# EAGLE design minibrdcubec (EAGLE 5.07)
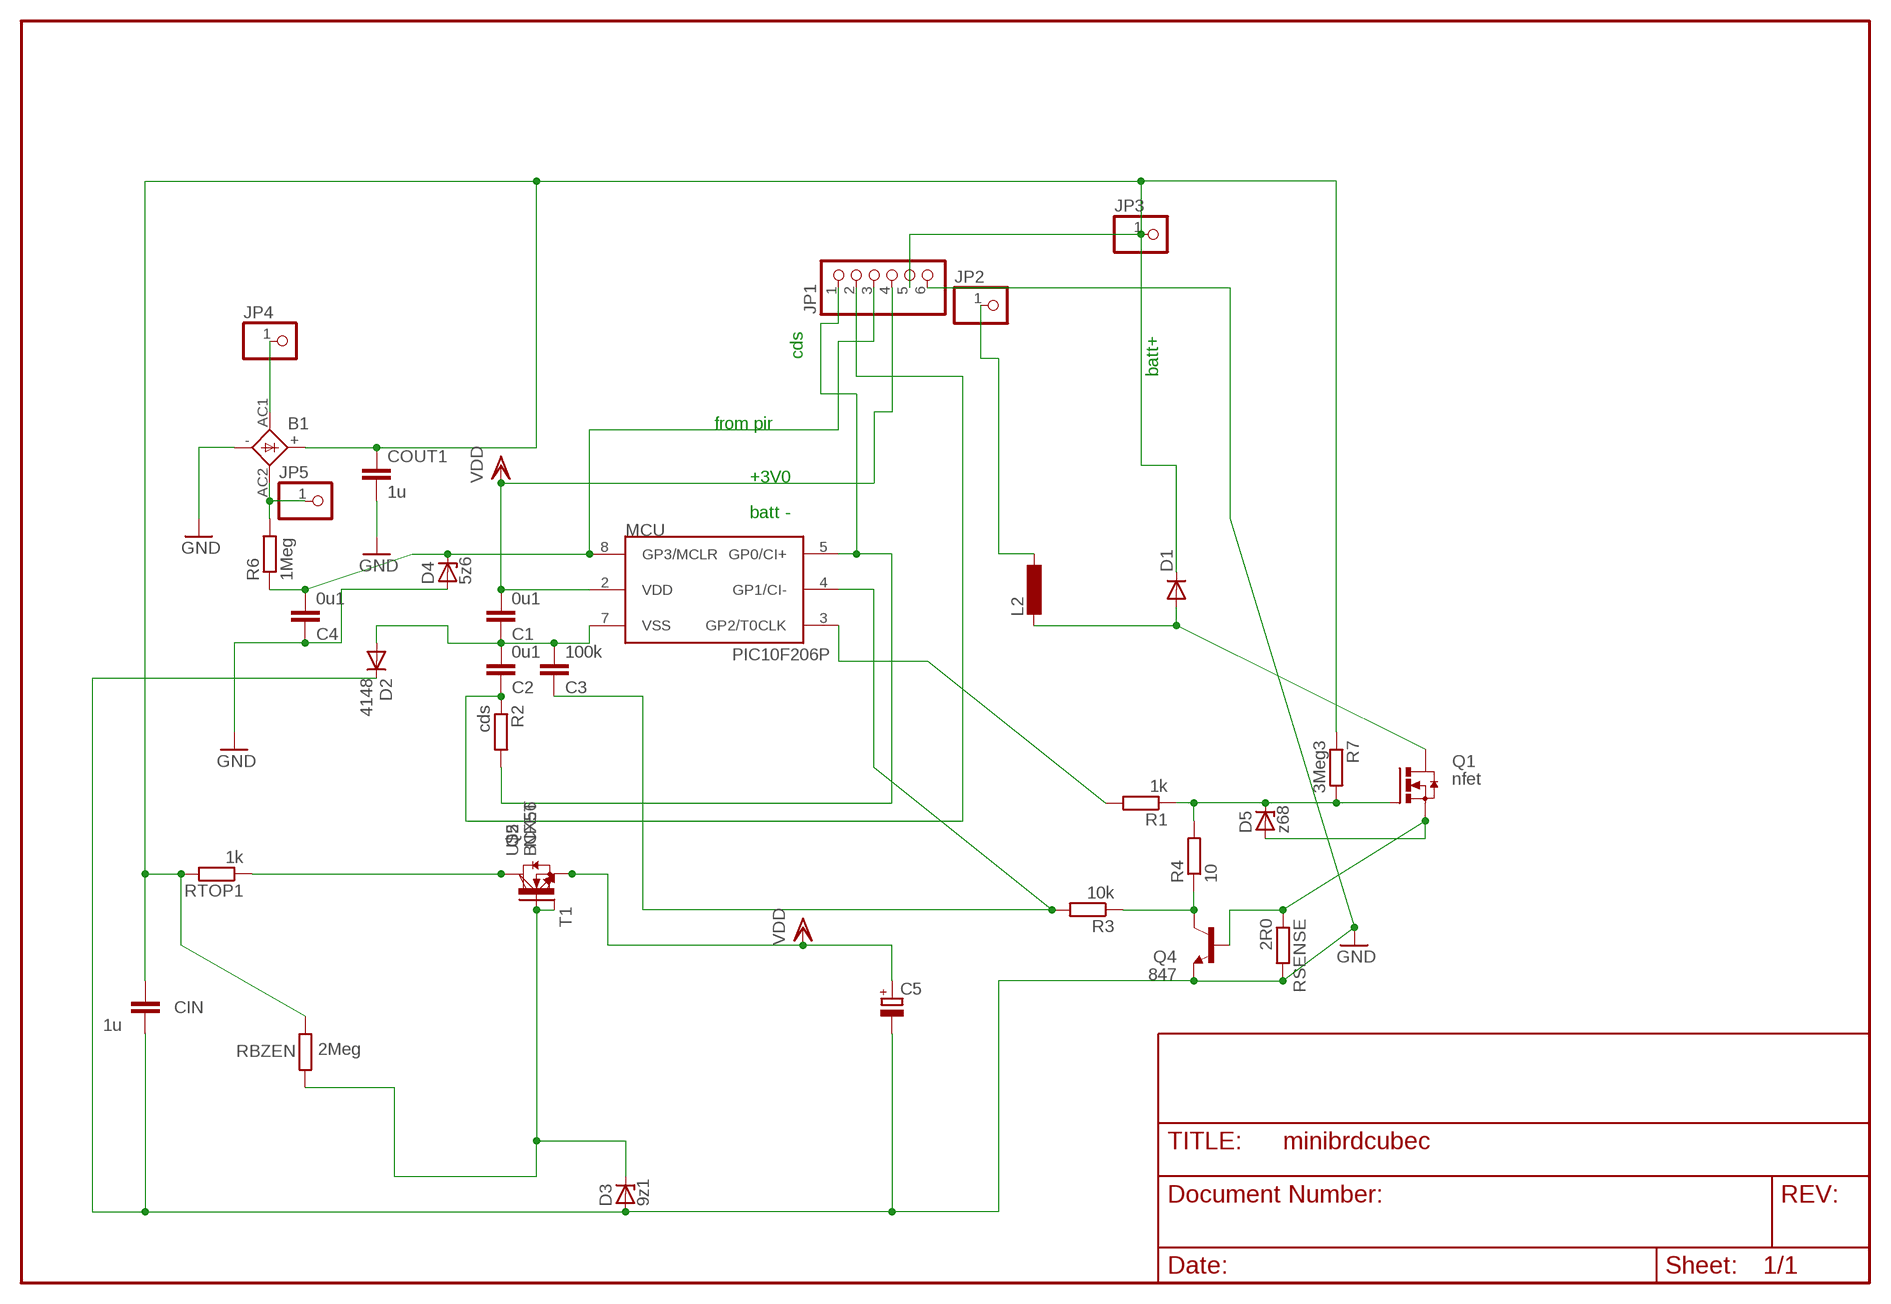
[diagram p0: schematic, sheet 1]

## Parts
B1  1KAB  [1KAB]
C1  0u1  C-EUC1206  [C1206]
C2  0u1  C-EUC0805  [C0805]
C3  100k  C-EUC1206  [C1206]
C4  0u1  C-EUC1206  [C1206]
C5  CPOL-EUSANYO_SMD_B6  [SANYO-OSCON_SMD_B6]
CIN  1u  C-EU050-024X044  [C050-024X044]
COUT1  1u  C-EU075-032X103  [C075-032X103]
D1  DIODE-SMC  [SMC]
D2  4148  1N4148MINIMELF  [MINIMELF]
D3  9z1  ZENER-DIODESOD80C  [SOD80C]
D4  5z6  ZENER-DIODESOD80C  [SOD80C]
D5  z68  ZENER-DIODESOD80C  [SOD80C]
JP1  PINHD-1X6  [1X06BOX]
JP2  PINHD-1X11X0.4  [1X01]
JP3  PINHD-1X11X0.4  [1X01]
JP4  PINHD-1X11X0.4  [1X01]
JP5  PINHD-1X11X0.4  [1X01]
L2  L-EU0207-17  [0207/17L]
MCU  PIC10F206P  [DIL8]
Q1  nfet  N-HEXFET_DPAK-  [TO252]
Q4  847  BC847ASMD  [SOT23]
Q5  NFET  N-HEXFET_DPAK-  [TO252]
R1  1k  R-EU_R0805  [R0805]
R2  cds  R-EU_0204/2V  [0204V]
R3  10k  R-EU_R1206  [R1206]
R4  10  R-EU_R0603  [R0603]
R6  1Meg  R-EU_0207/20  [0207/20]
R7  3Meg3  R-EU_0207/10  [0207/10]
RBZEN  2Meg  R-EU_0204/7  [0204/7]
RSENSE  2R0  R-EU_0207/15  [0207/15]
RTOP1  1k  R-EU_R1206  [R1206]
T1  -NPN-TO126V  [TO126V]
U$2  BCX56  [SOT223]

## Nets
AC1: B1.AC1 JP4.1
AC2: B1.AC2 JP5.1 R6.2
C: Q5.3(D) RTOP1.1 T1.2(C) U$2.2(C)
CB: D3.C Q5.1(G) RBZEN.2 T1.3(B) U$2.1(B)
GND: B1.- C4.1 C5.- CIN.2 COUT1.2 D2.C D3.A D4.A JP1.6 Q4.2(E) RSENSE.2
HOT: D1.A L2.2 Q1.3(D)
LED-: JP2.1 L2.1
N$1: Q4.3(C) R3.1 R4.1
N$2: JP1.1 MCU.5(GP0/CI+) R2.2
N$3: C1.1 C2.2 C3.2 D2.A MCU.7(VSS)
N$4: C3.1 MCU.4(GP1/CI-) R3.2
N$6: C4.2 D4.C JP1.3 MCU.8(GP3/MCLR) R6.1
N$7: D5.C Q1.1(G) R1.1 R4.2 R7.2
N$11: C2.1 JP1.2 R2.1
N$14: MCU.3(GP2/T0CLK) R1.2
N$17: D5.A Q1.2(S) Q4.1(B) RSENSE.1
VDD: C1.2 C5.+ JP1.4 MCU.2(VDD) Q5.2(S) T1.1(E) U$2.3(E)
VPLUS: B1.+ CIN.1 COUT1.1 D1.C JP1.5 JP3.1 R7.1 RBZEN.1 RTOP1.2

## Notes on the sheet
- cds
- batt+
- from pir
- +3V0
- batt -

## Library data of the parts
B1 = rectifier:1KAB: RECTIFIER grid 5,08 x 5,08 mm
C1-C4 CIN COUT1 = rcl:C-EU: CAPACITOR, European symbol
C5 = rcl-2:CPOL-EU: POLARIZED CAPACITOR, European symbol
D1 = diode-1:DIODE-: DIODE
D2 = diode-1:1N4148: DIODE
D3-D5 = diode:ZENER-DIODE: Z-Diode
JP1 = pinhead:PINHD-1X6: PIN HEADER
JP2-JP5 = pinhead:PINHD-1X1: PIN HEADER
L2 = rcl:L-EU: INDUCTOR, European symbol
MCU = microchip-3:PIC10F2*: uPC nW 0,25/0,5k Program Flash memory Comparator
Q1 Q5 = transistor-power:N-HEXFET_?-*: HEXFET® Power MOSFET
Q4 = transistor-npn:BC847*: NPN Transistor
R1-R4 R7 RBZEN RSENSE RTOP1 = rcl:R-EU_: RESISTOR, European symbol
R6 = rcl-2:R-EU_: RESISTOR, European symbol
T1 = transistor:*-NPN-: NPN Transistror BF959 corrected 2008.03.06
U$2 = transistor-power:BCX56

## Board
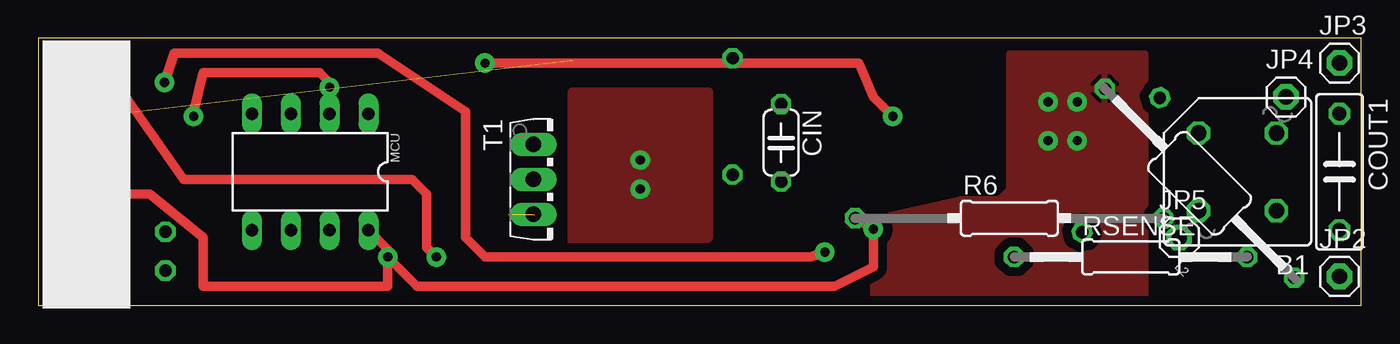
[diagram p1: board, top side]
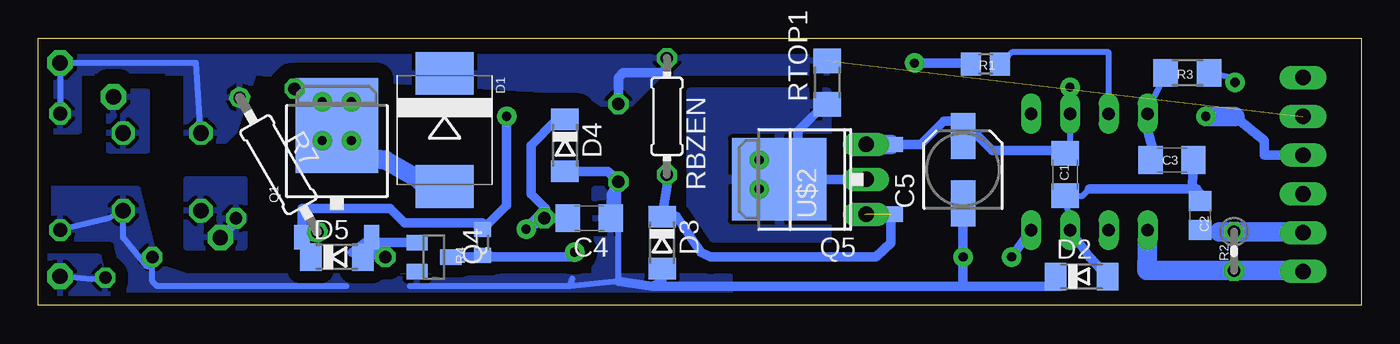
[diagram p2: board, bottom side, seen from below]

Size 86.52 x 17.5 mm. Coordinates in mm from the lower left corner, seen from the top.
Outline: 0,0 86.52,0 86.52,17.5 0,17.5 0,0
Copper layers (1*16): Top 0.035mm / dielectric 1.5mm / Bottom 0.035mm
Design rules "default *": minimum track width 10mil, minimum drill 24mil, track to track 8mil, track to pad 8mil, pad to pad 8mil, via to via 8mil, smd to smd 8mil, copper to edge 20mil, drill to drill 8mil, minimum pad ring 10mil, minimum via ring 8mil, stop-mask expansion 4mil, vias tented up to drill 0mil, thermal gap 10mil

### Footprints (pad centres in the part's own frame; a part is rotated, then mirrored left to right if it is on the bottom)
1KAB = drill 1.016 octagon: + 2.54,-2.54; - -2.54,2.54; AC1 -2.54,-2.54; AC2 2.54,2.54
C1206 = smd 1.6 x 1.8: 1 -1.4,0; 2 1.4,0
C0805 = smd 1.3 x 1.5: 1 -0.95,0; 2 0.95,0
SANYO-OSCON_SMD_B6 = smd 3 x 1.6: + 2.2,0; - -2.2,0
C050-024X044 = drill 0.813 octagon: 1 -2.54,0; 2 2.54,0
C075-032X103 = drill 0.914 octagon: 1 -3.81,0; 2 3.81,0
SMC = smd 2.8 x 3.8: A 3.7,0; C -3.7,0
MINIMELF = smd 1.4 x 1.8: A 1.7,0; C -1.7,0
SOD80C = smd 1.4 x 1.8: A 1.7,0; C -1.7,0
1X06BOX = drill 1.016 long: 1 -6.35,0; 2 -3.81,0; 3 -1.27,0; 4 1.27,0; 5 3.81,0; 6 6.35,0
1X01 = drill 1 pad 1.676 octagon: 1 0,0
0207/17L = drill 0.813 octagon: 1 -8.75,0; 2 8.75,0
DIL8 = drill 0.813 long: 1 -3.81,-3.81; 2 -1.27,-3.81; 3 1.27,-3.81; 4 3.81,-3.81; 5 3.81,3.81; 6 1.27,3.81; 7 -1.27,3.81; 8 -3.81,3.81
TO252 = smd 1 x 1.6: 1 -2.28,-3.53; 2 2.28,-3.53 | smd 5.4 x 6.2: 3 0,3.77
SOT23 = smd 1 x 1.4: 1 -0.95,-1.1; 2 0.95,-1.1; 3 0,1.1
R0805 = smd 1.3 x 1.5: 1 -0.95,0; 2 0.95,0
0204V = drill 0.813 octagon: 1 -1.27,0; 2 1.27,0
R1206 = smd 1.6 x 1.803: 1 -1.422,0; 2 1.422,0
R0603 = smd 1 x 1.1: 1 -0.85,0; 2 0.85,0
0207/20 = drill 0.813 octagon: 1 -10.08,0; 2 10.08,0
0207/10 = drill 0.813 octagon: 1 -5.08,0; 2 5.08,0
0204/7 = drill 0.813 octagon: 1 -3.81,0; 2 3.81,0
0207/15 = drill 0.813 octagon: 1 -7.62,0; 2 7.62,0
TO126V = drill 1.016 long: 1 -2.286,-1.27; 2 0,-1.27; 3 2.286,-1.27
SOT223 = smd 1.219 x 2.235: 1 -2.311,-3.099; 2 0,-3.099; 3 2.311,-3.099 | smd 3.6 x 2.2: 4 0,3.099

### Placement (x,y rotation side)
B1  78.42,8.75 180 top
C1  19.37,8.57 90 bottom
C2  10.54,5.91 90 bottom
C3  12.38,9.53 0 bottom
C4  50.48,5.71 180 bottom
C5  26.04,8.89 90 bottom
CIN  48.58,10.65 270 top
COUT1  85.09,8.75 270 top
D1  59.94,11.49 270 bottom
D2  18.3,1.91 0 bottom
D3  45.72,4.13 270 bottom
D4  52.07,10.48 270 bottom
D5  66.99,3.17 0 bottom
JP1  3.81,8.57 90 top
JP2  85.09,1.91 0 top
JP3  85.09,15.88 0 top
JP4  81.6,13.65 0 top
JP5  74.61,4.45 0 top
L2  75.94,8.01 135 top
MCU  17.78,8.75 180 top
Q1  66.99,8 0 bottom
Q4  60.64,3.17 270 bottom
Q5  34.29,8.26 90 bottom
R1  24.57,15.81 0 bottom
R2  8.32,3.56 270 bottom
R3  11.37,15.24 180 bottom
R4  57.47,4.13 90 bottom
R6  63.5,5.71 0 top
R7  70.8,9.21 300 bottom
RBZEN  45.4,12.38 270 bottom
RSENSE  71.44,3.17 0 top
RTOP1  34.92,14.61 90 bottom
T1  33.66,8.26 270 top
U$2  35.56,8.26 90 bottom

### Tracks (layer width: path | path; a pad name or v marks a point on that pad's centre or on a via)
AC1
  pour Bottom (isolate 0.61): 79.38,13.97 81.92,13.97 81.92,10.16 79.38,10.16
AC2
  Bottom 0.406: B1.AC2 75.42,6.35
  Bottom 0.61: R6.2 73.58,5.48 JP5.1
  pour Bottom (isolate 0.813, rank 2): 73.03,3.81 73.03,8.26 76.83,8.26 76.83,3.81
C  (via drill 0.6 pad 1.27)
  Bottom 0.406: T1.2 U$2.2 | v39.37,9.53 38.73,9.53 38.73,8.89
  Bottom 0.61: 38.73,8.89 38.1,8.26 36.83,8.26 | U$2.2 36.83,8.26 | RTOP1.1 35.08,13.18 36.83,11.43 36.83,8.26
  other vias: 39.37,7.62
  pour Bottom (isolate 0.61, rank 4): 34.92,13.97 43.81,13.97 43.81,12.06 43.81,4.45 42.55,3.17 34.92,3.17
  pour Top (isolate 0.61, rank 4): 34.92,13.97 43.81,13.97 43.81,12.06 43.81,4.45 42.55,3.17 34.92,3.17
CB  (2 unrouted)
  Bottom 0.61: Q5.1 30.76,4.09 31.75,3.17 42.55,3.17 43.18,3.49 44.77,5.83 D3.C 45.4,7.79 RBZEN.2
  Bottom 1.27: T1.3
GND  (via drill 0.6 pad 1.27)
  Top 0.61: JP1.6 4.13,14.61 5.08,14.61 9.53,8.26 24.45,8.26 25.4,7.3 25.4,3.81 v26.04,3.17
  Bottom 0.406: 66.36,1.27 78.74,1.27 79.06,1.59 RSENSE.2 79.38,2.54 80.96,4.45 B1.- 81.92,5.71 COUT1.2 | 51.75,1.27 48.58,1.59 CIN.2 | 51.75,1.27 62.23,1.27 | 19.68,1.27 D2.C | 51.75,1.27 51.58,1.76
  Bottom 0.61: 26.04,1.27 19.68,1.27 | 26.04,1.27 46.35,1.27 | 46.35,1.27 48.58,1.59 | C4.1 49.03,7.3 CIN.2 49.24,8.78 D4.A | 26.04,1.27 v26.04,3.17 C5.- | D3.A 45.72,1.59 46.35,1.27
  pour Bottom (isolate 0.813, rank 4): 80.01,7.62 85.72,7.62 85.72,3.81 83.19,3.81 81.28,0.64 41.27,0.64 41.27,1.91 48.9,1.91 48.9,7.62 50.16,7.62 50.16,1.91 76.83,1.91 78.74,2.54
HOT  (via drill 0.6 pad 1.27)
  Bottom 0.406: 65.3,9.7 Q1.3 66.99,13.02 67.31,13.34 68.9,13.02 | 68.9,13.02 68.58,12.7 | 68.9,13.02 69.22,13.34 69.22,13.97 67.94,13.97 L2.2
  Bottom 1.27: D1.A 61.13,7.79 61.59,8.26 63.82,9.53 65.3,9.7
  other vias: 66.04,10.79 67.94,10.79 67.94,13.34 66.04,13.34
  pour Top (isolate 0.61): 63.5,16.51 72.39,16.51 72.39,0.64 54.61,0.64 54.61,5.71 60.33,6.99 62.87,6.99 63.5,7.62
LED-
  Bottom 0.406: L2.1 83,1.73 JP2.1
  pour Bottom (isolate 0.61, rank 3): 82.55,3.17 86.36,3.17 86.36,0.64 81.92,0.64
N$1  (via drill 0.6 pad 1.27)
  Top 0.61: v51.44,3.49 50.48,3.17 29.21,3.17 27.94,4.45 27.94,12.7 22.23,16.51 8.89,16.51 v8.26,14.61
  Bottom 0.406: v8.26,14.61 8.57,14.92 R3.1
  Bottom 0.61: 56.52,3.17 51.75,3.17 v51.44,3.49 | 56.52,3.17 Q4.3 | 56.52,3.17 R4.1
N$2
  Bottom 0.406: JP1.1 4.06,2.29
  Bottom 1.27: 4.06,2.29 R2.2 14.03,2.29 MCU.5
N$3
  Bottom 0.406: MCU.7 19.05,5.58 C1.1 18.23,7.17 17.78,7.62 | 10.77,7.62 11.05,7.81
  Bottom 0.61: D2.A 17.78,3.17 MCU.7 | 17.78,7.62 10.77,7.62 10.54,7.33 C2.2 | 11.05,7.81 C3.2
N$4
  Bottom 0.406: R3.2 13.97,12.79 MCU.4 13.97,11.43 | C3.1 13.65,10.35
  Bottom 0.61: 13.65,10.35 13.97,11.43
N$6  (via drill 0.6 pad 1.27)
  Top 0.61: MCU.8 22.86,3.67 v22.86,3.17 | JP1.3 7.3,7.3 10.79,4.45 10.79,1.27 22.86,1.27 v22.86,3.17 | v22.86,3.17 24.77,1.27 52.07,1.27 54.61,2.54 v54.61,5 R6.1
  Bottom 0.61: v22.86,3.17 MCU.8 | D4.C 52.18,12.06 52.7,12.06 54.29,10.48 54.29,7.3 53.34,6.35 v54.61,5 53.26,5.71 C4.2
N$7  (via drill 0.6 pad 1.27)
  Top 0.61: v29.21,15.88 53.66,15.88 54.61,13.65 55.24,13.02 v55.88,12.38
  Bottom 0.61: 69.27,4.76 D5.C | v29.21,15.88 26.22,15.88 R1.1 | v55.88,12.38 55.88,6.57 R4.2 57.47,5.4 62.55,5.4 63.5,6.35 69.27,6.35 69.27,4.76 | 69.27,4.76 68.31,4.76 R7.2 | 69.27,4.76 Q1.1
N$11
  Bottom 0.406: 9.27,4.83 C2.1 | JP1.2 4.06,4.83
  Bottom 1.27: 9.27,4.83 R2.1 4.06,4.83
N$14
  Bottom 0.406: MCU.3 16.51,16.57 22.86,16.57 23.56,15.81 R1.2
N$17
  Bottom 0.406: 64.42,3.46 Q1.2 | RSENSE.1 64.77,3.17
  Bottom 0.61: 64.77,3.17 64.42,3.46 | Q4.1 62.72,4.13 64.45,4.13 RSENSE.1 | D5.A 65.98,3.49 Q1.2
VDD  (via drill 0.6 pad 1.27)
  Top 0.61: v10.16,12.38 10.16,12.7 10.79,15.24 18.41,15.24 19.05,14.61 v19.05,14.29 | MCU.2 19.05,12.7
  Bottom 0.406: 19.05,12.7 MCU.2 19.05,10.29 C1.2 | T1.1 32.44,10.54 U$2.3
  Bottom 0.61: JP1.4 6.35,9.84 6.35,10.79 8.26,12.38 | v19.05,14.29 MCU.2 | Q5.2 28.84,10.54 27.3,12.06 26.04,12.06 C5.+ 25.06,11.09 24.13,10.16 19.55,10.16 C1.2
  Bottom 1.27: 8.26,12.38 v10.16,12.38 | Q5.2 T1.1
VPLUS  (1 unrouted)
  Bottom 0.406: D1.C 60.58,16.13 61.59,15.24 | B1.+ 76.2,15.88 JP3.1 COUT1.1
  Bottom 0.61: CIN.1 48.58,14.92 48.26,15.24 45.57,15.24 RBZEN.1
  pour Bottom (isolate 1.016, rank 3): 86.36,11.43 83.82,11.43 83.82,15.24 76.83,15.24 76.83,10.79 74.3,10.79 73.66,11.43 72.39,15.24 50.8,13.97 48.9,12.7 48.26,12.7 45.72,15.24 34.92,15.24 34.29,17.14 86.36,17.14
